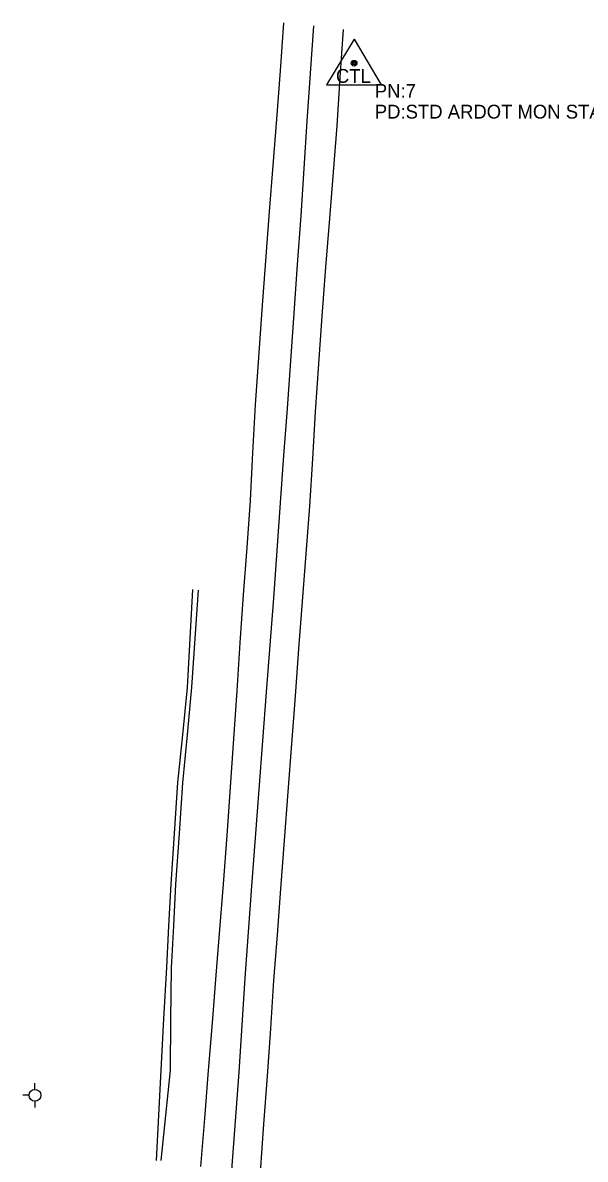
# Model space of a CAD drawing. Extents: x 1734049 to 1769984, y 344166 to 379510.
# Drawn here: x 1736157.4 to 1736361, y 378661.3 to 379072.5 of the extents above; entities that cross this region are included whole.
import ezdxf

# ---------------------------------------------------------------- set-up
doc = ezdxf.new("R2010")
doc.units = 0
for name, color, linetype in [('S_DITCHLINE', 7, 'Continuous'), ('S_EDGE_PAVEMENT', 7, 'Continuous'), ('S_PAVEMENT_CROWN', 7, 'Continuous'), ('S_PRIMARY_CTL', 7, 'Continuous'), ('S_PRIMARY_CTL_ANNOT', 7, 'Continuous'), ('S_UTILITY_POLE', 7, 'Continuous')]:
    doc.layers.add(name, color=color, linetype=linetype)

msp = doc.modelspace()

# ---------------------------------------------------------------- linework, layer by layer
at = {"layer": 'S_DITCHLINE'}
for points in [[(1736205.89, 378660.93), (1736206.71, 378677.25), (1736207.53, 378693.56), (1736208.55, 378712.16), (1736209.57, 378730.76), (1736210.36, 378745.79), (1736211.16, 378760.81), (1736212.38, 378779.24), (1736213.61, 378797.67), (1736215.36, 378814.85), (1736217.11, 378832.02), (1736218.07, 378849.77), (1736219.03, 378867.53)], [(1736207.58, 378660.87), (1736209.22, 378677.2), (1736210.87, 378693.52), (1736211.09, 378712.07), (1736211.32, 378730.62), (1736212.11, 378745.77), (1736212.9, 378760.93), (1736214.15, 378779.25), (1736215.4, 378797.58), (1736217.03, 378814.86), (1736218.65, 378832.14), (1736219.86, 378849.72), (1736221.07, 378867.29)]]:
    msp.add_lwpolyline(points, dxfattribs=at)
at = {"layer": 'S_EDGE_PAVEMENT'}
for points in [[(1736251.77, 379072.52), (1736250.55, 379055.08), (1736249.33, 379037.65), (1736247.96, 379020.91), (1736246.58, 379004.18), (1736245.25, 378986.4), (1736243.91, 378968.62), (1736242.72, 378951.42), (1736241.54, 378934.23), (1736240.65, 378916.93), (1736239.77, 378899.64), (1736238.5, 378882.62), (1736237.23, 378865.6), (1736236.06, 378848.23), (1736234.9, 378830.85), (1736233.72, 378813.42), (1736232.54, 378795.99), (1736231.26, 378778.46), (1736229.98, 378760.92), (1736228.66, 378744.45), (1736227.35, 378727.98), (1736225.97, 378710.74), (1736224.6, 378693.51), (1736223.18, 378676.09), (1736221.77, 378658.68)], [(1736273.38, 379070.09), (1736272.22, 379052.68), (1736271.06, 379035.27), (1736269.73, 379018.49), (1736268.4, 379001.71), (1736267.06, 378984.07), (1736265.72, 378966.42), (1736264.52, 378949.09), (1736263.31, 378931.76), (1736262.27, 378914.71), (1736261.23, 378897.67), (1736259.89, 378880.42), (1736258.56, 378863.17), (1736257.28, 378846.06), (1736256, 378828.94), (1736254.7, 378811.59), (1736253.39, 378794.23), (1736252.08, 378776.7), (1736250.76, 378759.18), (1736249.51, 378742.58), (1736248.25, 378725.98), (1736247.09, 378708.68), (1736245.92, 378691.37), (1736244.61, 378674.03), (1736243.31, 378656.68)]]:
    msp.add_lwpolyline(points, dxfattribs=at)
at = {"layer": 'S_PAVEMENT_CROWN'}
msp.add_lwpolyline([(1736262.65, 379071.37), (1736261.46, 379054.15), (1736260.27, 379036.93), (1736259.17, 379019.81), (1736258.06, 379002.7), (1736256.78, 378985.09), (1736255.5, 378967.48), (1736254.33, 378950.25), (1736253.17, 378933.01), (1736251.87, 378915.91), (1736250.57, 378898.81), (1736249.36, 378881.55), (1736248.15, 378864.29), (1736246.86, 378847.29), (1736245.56, 378830.29), (1736244.2, 378812.7), (1736242.84, 378795.1), (1736241.56, 378777.61), (1736240.29, 378760.12), (1736239.08, 378743.49), (1736237.86, 378726.85), (1736236.74, 378709.88), (1736235.62, 378692.91), (1736234.33, 378675.16), (1736233.05, 378657.41)], dxfattribs=at)
at = {"layer": 'S_PRIMARY_CTL'}
for p, q in [((1736277.36, 379066.55), (1736267.33, 379050.04)), ((1736277.36, 379066.55), (1736287.19, 379050.04)), ((1736267.33, 379050.04), (1736287.19, 379050.04))]:
    msp.add_line(p, q, dxfattribs=at)
for radius in [1.04, 0.609, 0.344]:
    msp.add_circle((1736277.36, 379057.85), radius, dxfattribs=at)
at = {"layer": 'S_UTILITY_POLE'}
for p, q in [((1736161.86, 378686.61), (1736161.86, 378688.86)), ((1736159.77, 378684.48), (1736157.44, 378684.48)), ((1736161.94, 378680.07), (1736161.94, 378682.39))]:
    msp.add_line(p, q, dxfattribs=at)
msp.add_circle((1736161.86, 378684.5), 2.13, dxfattribs=at)

# ---------------------------------------------------------------- texts
at = {"layer": 'S_PRIMARY_CTL'}
msp.add_text('CTL', height=5, rotation=360, dxfattribs=at).set_placement((1736270.78, 379050.77))
at = {"layer": 'S_PRIMARY_CTL_ANNOT'}
for s, p in [('PN:7', (1736284.86, 379045.35)), ('PD:STD ARDOT MON STAMPED:PN:7', (1736284.86, 379037.85))]:
    msp.add_text(s, height=5, dxfattribs=at).set_placement(p)

doc.saveas('drawing.dxf')
